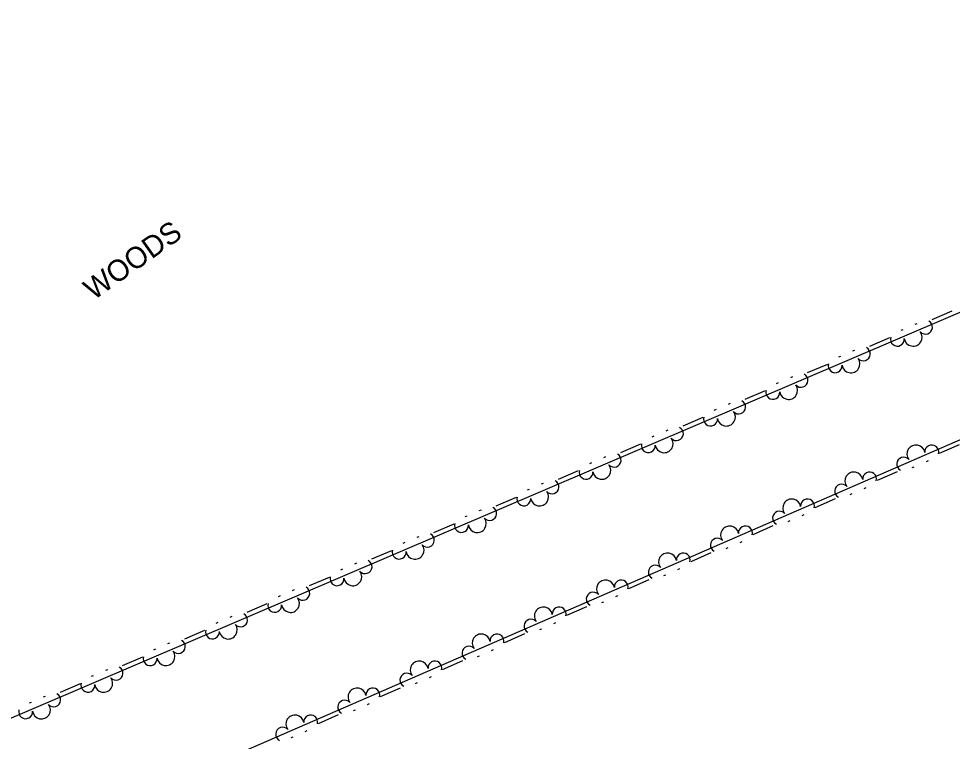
# Model space of a CAD drawing. Extents: x 1577032 to 1581865, y 611492 to 615011.
# Drawn here: x 1578479.3 to 1578654.5, y 612619.6 to 612755.3 of the extents above; entities that cross this region are included whole.
import ezdxf

# ---------------------------------------------------------------- set-up
doc = ezdxf.new("R2010")
doc.units = 0
doc.layers.add('Exist Vegetation Woods Line Text', color=7, linetype='Continuous')
doc.layers.add('Old_Level_11', color=7, linetype='Continuous')

msp = doc.modelspace()

# ---------------------------------------------------------------- linework, layer by layer
at = {"layer": 'Old_Level_11'}
for points in [[(1578854.39, 612741.35), (1578805.77, 612755.29), (1578776.22, 612749.53), (1578748.88, 612739.86), (1578397.75, 612589.78), (1578202.57, 612520.47)], [(1578219.14, 612501.33), (1578402.75, 612566.18), (1578724.72, 612706.14), (1578817.97, 612709.56)], [(1578654.46, 612700.39), (1578650.68, 612698.78)], [(1578645.24, 612696.9), (1578644.87, 612696.74)], [(1578647.88, 612698.03), (1578647.5, 612697.86)], [(1578642.76, 612695.39), (1578638.99, 612693.78)], [(1578636.19, 612693.03), (1578635.81, 612692.87)], [(1578633.55, 612691.9), (1578633.18, 612691.74)], [(1578631.07, 612690.4), (1578627.3, 612688.79)], [(1578624.5, 612688.03), (1578624.13, 612687.87)], [(1578621.86, 612686.91), (1578621.49, 612686.74)], [(1578619.38, 612685.4), (1578615.61, 612683.79)], [(1578612.81, 612683.04), (1578612.44, 612682.88)], [(1578610.17, 612681.91), (1578609.79, 612681.75)], [(1578607.69, 612680.4), (1578603.92, 612678.79)], [(1578601.12, 612678.04), (1578600.75, 612677.88)], [(1578598.48, 612676.91), (1578598.1, 612676.75)], [(1578596, 612675.41), (1578592.23, 612673.8)], [(1578652.13, 612673.7), (1578655.89, 612675.33)], [(1578589.43, 612673.04), (1578589.06, 612672.88)], [(1578649.66, 612672.17), (1578650.03, 612672.34)], [(1578584.31, 612670.41), (1578580.54, 612668.8)], [(1578586.79, 612671.92), (1578586.41, 612671.75)], [(1578640.47, 612668.63), (1578644.23, 612670.26)], [(1578647.02, 612671.03), (1578647.4, 612671.19)], [(1578575.1, 612666.92), (1578574.72, 612666.76)], [(1578577.74, 612668.05), (1578577.36, 612667.89)], [(1578638, 612667.11), (1578638.37, 612667.27)], [(1578572.62, 612665.41), (1578568.85, 612663.8)], [(1578628.81, 612663.56), (1578632.57, 612665.19)], [(1578635.37, 612665.96), (1578635.74, 612666.13)], [(1578563.41, 612661.92), (1578563.04, 612661.76)], [(1578566.05, 612663.05), (1578565.67, 612662.89)], [(1578626.34, 612662.04), (1578626.72, 612662.2)], [(1578560.93, 612660.42), (1578557.16, 612658.8)], [(1578617.15, 612658.49), (1578620.91, 612660.13)], [(1578623.71, 612660.89), (1578624.08, 612661.06)], [(1578554.36, 612658.05), (1578553.98, 612657.89)], [(1578551.72, 612656.93), (1578551.35, 612656.77)], [(1578614.68, 612656.97), (1578615.06, 612657.13)], [(1578549.24, 612655.42), (1578545.47, 612653.81)], [(1578605.49, 612653.42), (1578609.25, 612655.06)], [(1578612.05, 612655.83), (1578612.42, 612655.99)], [(1578542.67, 612653.06), (1578542.29, 612652.9)], [(1578540.03, 612651.93), (1578539.66, 612651.77)], [(1578600.39, 612650.76), (1578600.76, 612650.92)], [(1578603.02, 612651.9), (1578603.4, 612652.07)], [(1578537.55, 612650.42), (1578533.78, 612648.81)], [(1578593.83, 612648.35), (1578597.59, 612649.99)], [(1578530.98, 612648.06), (1578530.61, 612647.9)], [(1578528.34, 612646.93), (1578527.96, 612646.77)], [(1578588.73, 612645.69), (1578589.1, 612645.85)], [(1578591.36, 612646.83), (1578591.74, 612647)], [(1578525.86, 612645.43), (1578522.09, 612643.82)], [(1578582.17, 612643.29), (1578585.93, 612644.92)], [(1578519.29, 612643.06), (1578518.91, 612642.9)], [(1578514.17, 612640.43), (1578510.4, 612638.82)], [(1578516.65, 612641.94), (1578516.27, 612641.77)], [(1578577.07, 612640.62), (1578577.45, 612640.78)], [(1578579.7, 612641.76), (1578580.08, 612641.93)], [(1578570.51, 612638.22), (1578574.27, 612639.85)], [(1578504.96, 612636.94), (1578504.58, 612636.78)], [(1578507.6, 612638.07), (1578507.22, 612637.91)], [(1578502.48, 612635.43), (1578498.71, 612633.82)], [(1578565.41, 612635.55), (1578565.79, 612635.71)], [(1578568.04, 612636.7), (1578568.42, 612636.86)], [(1578558.85, 612633.15), (1578562.61, 612634.78)], [(1578493.27, 612631.94), (1578492.89, 612631.78)], [(1578495.91, 612633.07), (1578495.53, 612632.91)], [(1578556.38, 612631.63), (1578556.76, 612631.79)], [(1578490.79, 612630.44), (1578487.02, 612628.83)], [(1578553.75, 612630.48), (1578554.13, 612630.65)], [(1578547.19, 612628.08), (1578550.95, 612629.71)], [(1578481.58, 612626.95), (1578481.2, 612626.79)], [(1578484.22, 612628.07), (1578483.84, 612627.91)], [(1578544.73, 612626.56), (1578545.1, 612626.72)], [(1578535.53, 612623.01), (1578539.3, 612624.65)], [(1578542.09, 612625.41), (1578542.47, 612625.58)], [(1578533.06, 612621.49), (1578533.44, 612621.65)], [(1578530.43, 612620.35), (1578530.81, 612620.51)]]:
    msp.add_lwpolyline(points, dxfattribs=at)
for centre, radius, start, end in [((1578649.5, 612697.38), 1.3, 221.5777, 62.3743), ((1578647.18, 612695.5), 1.69, 189.1065, 37.179), ((1578644.22, 612695.12), 1.3, 163.9112, 4.7078), ((1578637.81, 612692.38), 1.3, 221.5777, 62.3743), ((1578635.49, 612690.5), 1.69, 189.1065, 37.179), ((1578632.53, 612690.13), 1.3, 163.9112, 4.7078), ((1578626.12, 612687.39), 1.3, 221.5777, 62.3743), ((1578623.8, 612685.5), 1.69, 189.1065, 37.179), ((1578620.84, 612685.13), 1.3, 163.9112, 4.7078), ((1578614.43, 612682.39), 1.3, 221.5777, 62.3743), ((1578612.11, 612680.51), 1.69, 189.1065, 37.179), ((1578609.15, 612680.13), 1.3, 163.9112, 4.7078), ((1578602.74, 612677.39), 1.3, 221.5777, 62.3743), ((1578597.46, 612675.14), 1.3, 163.9112, 4.7078), ((1578600.42, 612675.51), 1.69, 189.1065, 37.179), ((1578647.71, 612673.56), 1.69, 9.4589, 217.5314), ((1578650.67, 612673.96), 1.3, 344.2636, 185.0602), ((1578591.05, 612672.4), 1.3, 221.5777, 62.3743), ((1578645.41, 612671.67), 1.3, 41.9301, 242.7266), ((1578585.77, 612670.14), 1.3, 163.9112, 4.7078), ((1578588.73, 612670.51), 1.69, 189.1065, 37.179), ((1578636.05, 612668.5), 1.69, 9.4589, 217.5314), ((1578639.01, 612668.89), 1.3, 344.2636, 185.0602), ((1578579.36, 612667.4), 1.3, 221.5777, 62.3743), ((1578633.75, 612666.6), 1.3, 41.9301, 242.7266), ((1578574.08, 612665.14), 1.3, 163.9112, 4.7078), ((1578577.04, 612665.52), 1.69, 189.1065, 37.179), ((1578624.39, 612663.43), 1.69, 9.4589, 217.5314), ((1578627.35, 612663.82), 1.3, 344.2636, 185.0602), ((1578567.67, 612662.4), 1.3, 221.5777, 62.3743), ((1578565.35, 612660.52), 1.69, 189.1065, 37.179), ((1578622.09, 612661.53), 1.3, 41.9301, 242.7266), ((1578562.39, 612660.15), 1.3, 163.9112, 4.7078), ((1578612.73, 612658.36), 1.69, 9.4589, 217.5314), ((1578615.69, 612658.75), 1.3, 344.2636, 185.0602), ((1578555.98, 612657.41), 1.3, 221.5777, 62.3743), ((1578553.66, 612655.52), 1.69, 189.1065, 37.179), ((1578610.43, 612656.46), 1.3, 41.9301, 242.7266), ((1578550.7, 612655.15), 1.3, 163.9112, 4.7078), ((1578601.07, 612653.29), 1.69, 9.4589, 217.5314), ((1578604.03, 612653.68), 1.3, 344.2636, 185.0602), ((1578544.29, 612652.41), 1.3, 221.5777, 62.3743), ((1578598.77, 612651.39), 1.3, 41.9301, 242.7266), ((1578541.97, 612650.53), 1.69, 189.1065, 37.179), ((1578539.01, 612650.15), 1.3, 163.9112, 4.7078), ((1578589.42, 612648.22), 1.69, 9.4589, 217.5314), ((1578592.38, 612648.62), 1.3, 344.2636, 185.0602), ((1578532.6, 612647.41), 1.3, 221.5777, 62.3743), ((1578587.11, 612646.33), 1.3, 41.9301, 242.7266), ((1578530.28, 612645.53), 1.69, 189.1065, 37.179), ((1578527.32, 612645.16), 1.3, 163.9112, 4.7078), ((1578577.76, 612643.15), 1.69, 9.4589, 217.5314), ((1578580.72, 612643.55), 1.3, 344.2636, 185.0602), ((1578520.91, 612642.42), 1.3, 221.5777, 62.3743), ((1578575.45, 612641.26), 1.3, 41.9301, 242.7266), ((1578515.63, 612640.16), 1.3, 163.9112, 4.7078), ((1578518.59, 612640.53), 1.69, 189.1065, 37.179), ((1578566.1, 612638.09), 1.69, 9.4589, 217.5314), ((1578569.06, 612638.48), 1.3, 344.2636, 185.0602), ((1578509.22, 612637.42), 1.3, 221.5777, 62.3743), ((1578563.79, 612636.19), 1.3, 41.9301, 242.7266), ((1578503.94, 612635.16), 1.3, 163.9112, 4.7078), ((1578506.9, 612635.54), 1.69, 189.1065, 37.179), ((1578497.53, 612632.42), 1.3, 221.5777, 62.3743), ((1578554.44, 612633.02), 1.69, 9.4589, 217.5314), ((1578557.4, 612633.41), 1.3, 344.2636, 185.0602), ((1578552.13, 612631.12), 1.3, 41.9301, 242.7266), ((1578492.25, 612630.17), 1.3, 163.9112, 4.7078), ((1578495.21, 612630.54), 1.69, 189.1065, 37.179), ((1578485.84, 612627.43), 1.3, 221.5777, 62.3743), ((1578542.78, 612627.95), 1.69, 9.4589, 217.5314), ((1578545.74, 612628.34), 1.3, 344.2636, 185.0602), ((1578483.52, 612625.54), 1.69, 189.1065, 37.179), ((1578540.47, 612626.05), 1.3, 41.9301, 242.7266), ((1578480.56, 612625.17), 1.3, 163.9112, 4.7078), ((1578531.12, 612622.88), 1.69, 9.4589, 217.5314), ((1578534.08, 612623.27), 1.3, 344.2636, 185.0602), ((1578528.81, 612620.98), 1.3, 41.9301, 242.7266)]:
    msp.add_arc(centre, radius, start, end, dxfattribs=at)

# ---------------------------------------------------------------- texts
at = {"layer": 'Exist Vegetation Woods Line Text'}
msp.add_text('WOODS', height=4, rotation=35.38, dxfattribs=at).set_placement((1578493.3, 612702.32))

doc.saveas('drawing.dxf')
